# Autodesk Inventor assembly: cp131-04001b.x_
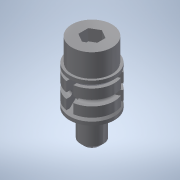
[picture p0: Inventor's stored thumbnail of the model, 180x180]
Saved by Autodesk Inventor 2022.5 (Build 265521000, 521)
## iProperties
Part Number: cp131-04001b.x_
Material: 一般
Document SubType Name: Assembly
Designer: ImaoCorp
Sending System: SOLIDWORKS 2017-2017317
MC: AMD64
MC_MODEL: Intel64 Family 6 Model 60 Stepping 3, GenuineIntel
OS: Windows_NT
FRU: Parasolid Version 29.0, build 201,  4-17-2017
FORMAT: text
GUISE: transmit
KEY: cp131-04001b
FILE: cp131-04001b.x_t
DATE: Thu Apr 04 16:36:33 2019
Author: ImaoCorp
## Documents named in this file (7)
- X:\14_SW2022-Inv2022\00_全2023-1023新製品(TCC)まで\c\cp131-04001b\CP131-04001B.iam
- X:\14_SW2022-Inv2022\00_全2023-1023新製品(TCC)まで\c\cp131-04001b\cp131-04001b_01.ipt
- X:\14_SW2022-Inv2022\00_全2023-1023新製品(TCC)まで\c\cp131-04001b\cp131-04001b_02.ipt
- X:\14_SW2022-Inv2022\00_全2023-1023新製品(TCC)まで\c\cp131-04001b\cp131-04001b_03.ipt
- X:\14_SW2022-Inv2022\00_全2023-1023新製品(TCC)まで\c\cp131-04001b\cp131-04001b_04.ipt
- X:\14_SW2022-Inv2022\00_全2023-1023新製品(TCC)まで\c\cp131-04001b\cp131-04001b_05.ipt
- X:\14_SW2022-Inv2022\00_全2023-1023新製品(TCC)まで\c\cp131-04001b\cp131-04001b_06.ipt
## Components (6 placed, 6 different names)
1. cp131-04001b_01
2. cp131-04001b_02
3. cp131-04001b_03
4. cp131-04001b_04
5. cp131-04001b_05
6. cp131-04001b_06
